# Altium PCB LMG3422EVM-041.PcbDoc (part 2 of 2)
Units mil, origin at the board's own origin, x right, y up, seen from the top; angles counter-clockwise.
Board outline 3001 x 1535.46 mil, 4 copper layers (Top Layer, MidLayer1, MidLayer2, Bottom Layer), stack 46.2 mil thick; 103 components, 73 nets, 350 pads, 858 vias.
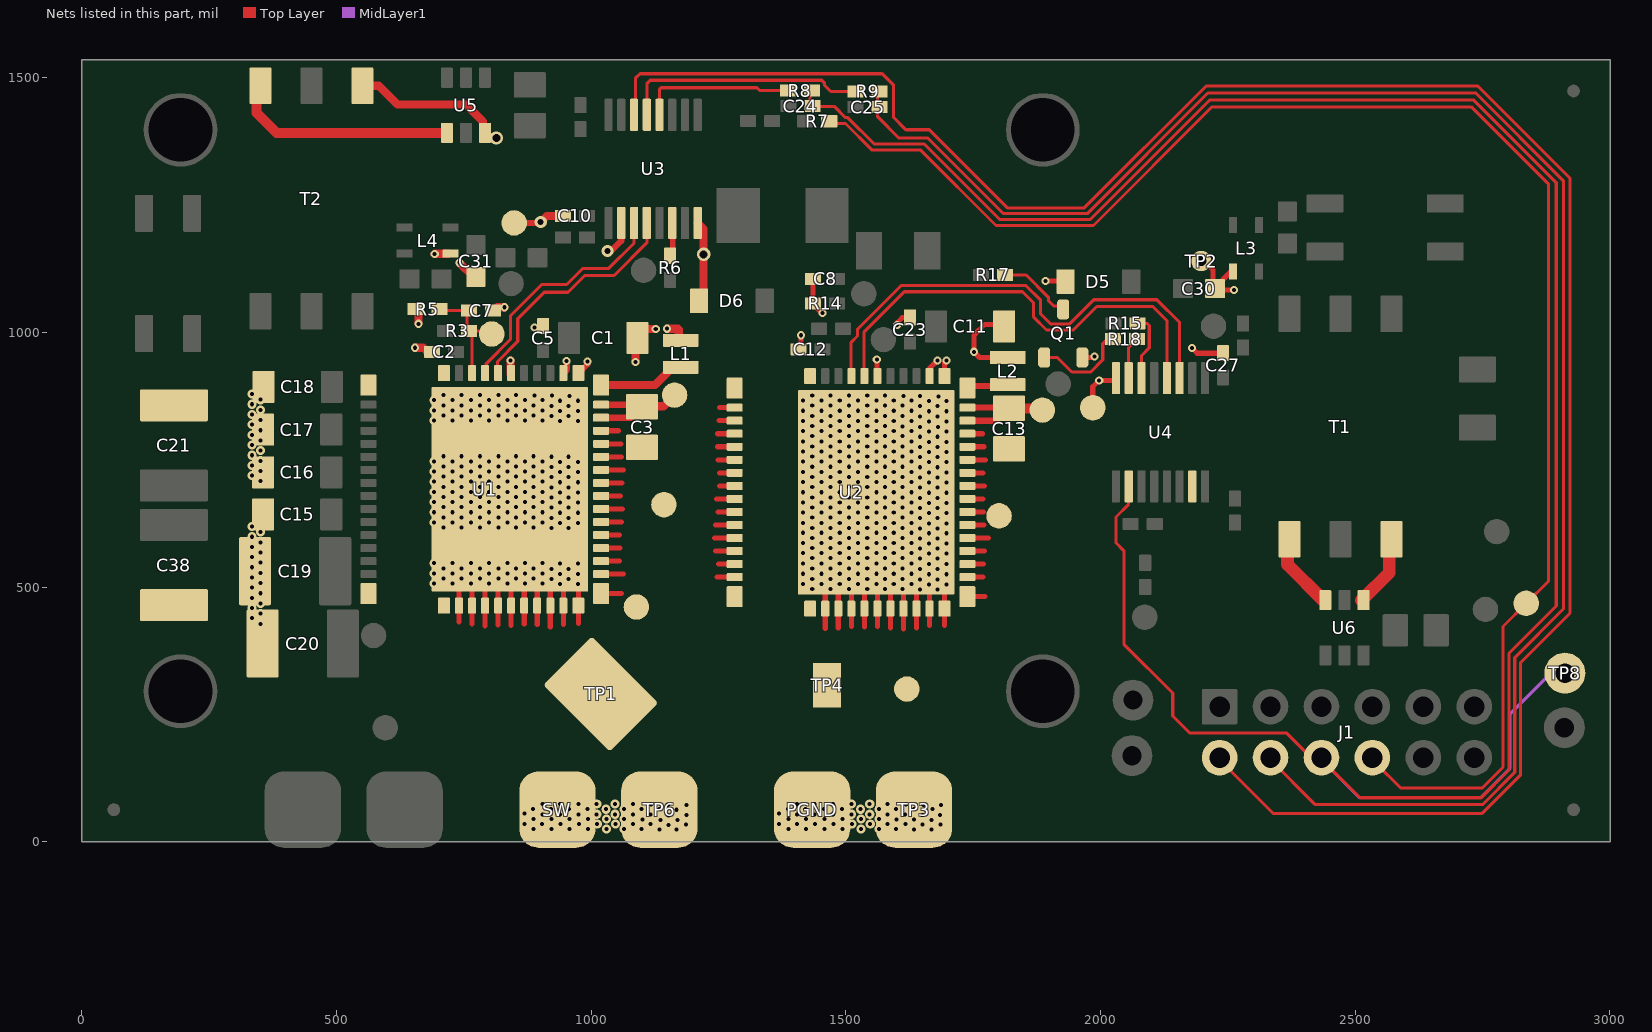
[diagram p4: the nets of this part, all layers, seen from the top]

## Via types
v1: diameter 18, hole 8, Top Layer to Bottom Layer, tented both sides, 781 vias
v2: diameter 16, hole 8, Top Layer to Bottom Layer, tented both sides, 44 vias
v3: diameter 26, hole 16, Top Layer to Bottom Layer, tented both sides, 17 vias
v4: diameter 24, hole 12, Top Layer to Bottom Layer, tented both sides, 6 vias
v5: diameter 20, hole 10, Top Layer to Bottom Layer, tented both sides, 6 vias
v6: diameter 16, hole 8, Top Layer to Bottom Layer, 3 vias
v7: diameter 20, hole 10, Top Layer to Bottom Layer, 1 vias

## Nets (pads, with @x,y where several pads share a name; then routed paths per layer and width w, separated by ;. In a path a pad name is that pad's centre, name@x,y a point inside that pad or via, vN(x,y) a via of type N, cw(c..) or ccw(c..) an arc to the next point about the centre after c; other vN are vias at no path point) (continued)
NetL1_2: L1.2 U1.43 | length 154.6
  Top Layer w16: U1.43@1019.69,896.57 1125.44,896.57 L1.2@1160,931.13
NetL2_2: L2.2 U2.43 | length 76.8
  Top Layer w12: U2.43@1738.35,894.72 1811.3,894.72 L2.2@1814,897.42
NetQ1_1: Q1.1 R18.2 | length 188.5
  Top Layer w6: Q1.1@1890.65,951 1915.53,951 1943.96,922.57 1981.02,922.57 2004.62,946.17 2004.62,959.83 2004.57,959.88 2004.57,978.19 R18.2@2019.38,993
NetQ1_3: Q1.3 R17.1 | length 149.2
  Top Layer w6: R17.1@1812,1116 1815.14,1112.86 1854.14,1112.86 1897.74,1069.26 1897.74,1062.65 1908.74,1051.65 1920.6,1051.65 Q1.3@1927,1045.24 ; Q1.3@1927,1045.49 Q1.3@1928.05,1045.49
NetR6_1: R6.1 U3.6 | length 65.9
  Top Layer w10: R6.1@1160.4,1148.51 U3.6@1160.4,1214.39
NetR8_2: R8.2 U3.12 | length 303.9
  Top Layer w6: U3.12@1130.4,1427.1 1134,1430.7 1134,1477.38 1137.12,1480.5 1325.79,1480.5 1331.65,1474.63 R8.2@1382.38,1474.63
NetR9_2: R9.2 U3.13 | length 483.5
  Top Layer w6: U3.13@1105.4,1427.1 1109.4,1431.1 1109.4,1488.47 1116.15,1495.22 1452.89,1495.22 1457.87,1490.24 1457.87,1485.96 1470.83,1473 R9.2@1515.38,1473
NetR15_1: R15.1 U4.6 | length 141.4
  Top Layer w6: R15.1@2065.92,1023 R15.1@2072.62,1023 ; R15.1@2072.62,1018 2091.47,1018 2095.87,1013.6 2095.87,969.87 2080.5,954.5 U4.6@2080.5,910.3
NetR18_1: R18.1 U4.7 | length 83.4
  Top Layer w6: U4.7@2055.5,910.3 2055.5,970.88 R18.1@2071.62,987
NetT1_1: T1.1 U6.3 | length 148.8
  Top Layer w25: T1.1@2367.24,593.74 2367.24,544.5 U6.3@2437.6,474.13
NetT1_3: T1.3 U6.1 | length 142.3
  Top Layer w25: U6.1@2512.4,474.13 2567.24,528.97 T1.3@2567.24,593.74
NetT2_1: T2.1 U5.3 | length 325.7
  Top Layer w16: T2.1@544,1484.26 583.24,1484.26 620,1447.5 754.7,1447.5 787.77,1414.43 787.77,1391.58 797.35,1382 v3(814,1382)
NetT2_3: T2.3 U5.1 | length 446.4
  Top Layer w20: T2.3@343.28,1491.26 343.28,1430.87 382.57,1391.58 U5.1@712.97,1391.58
OC_H: U1.50 U3.4 | length 484.6
  Top Layer w6: U1.50@816.18,918.35 816.18,942.74 856,982.56 856,1027 908,1079 954.62,1079 987.62,1112 1045.26,1112 1109.4,1176.13 U3.4@1109.4,1210.5 ; U3.4@1105.4,1214.5 U3.4@1109.4,1210.5 ; U3.4@1109.4,1214.78 U3.4@1109.4,1210.5
OC_L: U2.50 U4.4 | length 900.9
  Top Layer w6: U2.50@1536.18,918.35 1536.18,1001.18 1615,1080 1847,1080 1869,1058 1869,1030 1894,1005 1946.94,1005 1992.94,1051 2103,1051 2130.5,1023.5 U4.4@2130.5,910.3
OUTA: U4.15
PGND: C8.2 C11.1 C12.2 C13.2 C15.2 C16.2 C17.2 C18.2 C19.2 C20.2 C21.2 C23.1 C27.2 C30.2 C38.2 D5.2 L2.1 L3.1 pad.1@1620,299.94 pad.1@1801,639.94 pad.1@1985,852.27 PGND.1 Q1.2 R14.1 TP2.1 TP3.1 TP4.1 U2.18 U2.19 U2.20 U2.21 U2.22 U2.23 U2.24 U2.25 U2.26 U2.27 U2.28 U2.29 U2.30 U2.31 U2.32 U2.33 U2.34 U2.35 U2.36 U2.37 U2.38 U2.39 U2.40 U2.44 U2.45 U2.49 U2.55 U4.8 | length 1935
  Top Layer w10: C12.2@1407,967 1412.13,972.13 v2(1412.13,994.52) ; R14.1@1435.76,1057 C8.2@1435.76,1105.27 ; R14.1@1436.38,1054.62 1452.51,1038.49 v2(1454.37,1038.49) ; 1459.76,418.96 U2.18@1459.76,457.68 U2.55@1459.76,490.61 ; 1485.35,419.92 U2.19@1485.35,457.68 U2.55@1485.35,495 ; 1510.94,423.06 U2.20@1510.94,457.68 1510.94,484.94 ; 1536.53,422.28 U2.21@1536.53,457.68 U2.55@1536.53,496 ; v2(1561,947) 1561,919.12 U2.49@1561.77,918.35 ; 1562.12,422.88 U2.22@1562.12,457.68 U2.55@1562.12,495 ; 1587.71,419.56 U2.23@1587.71,457.68 U2.55@1587.71,495 ; v2(1601,1014.58) 1601,1019 1611,1029 C23.1@1622,1029 ; 1613.3,417.7 U2.24@1613.3,457.68 U2.55@1613.3,497 ; 1638.89,420.11 U2.25@1638.89,457.68 U2.55@1638.89,499 ; U2.45@1664.13,918.35 1664.13,929.13 v2(1680,945) ; 1664.48,424.78 U2.26@1664.48,457.68 U2.55@1664.48,498.5 ; U2.44@1693.66,918.35 1693.66,940.61 v2(1698,944.95) ; 1694.01,424.87 U2.27@1694.01,457.68 U2.55@1694.01,495 ; U2.28@1738.69,481.3 1773.3,481.3 ; U2.29@1738.69,519.68 1769.45,519.68 ; U2.30@1738.69,545.28 1770.72,545.28 ; U2.31@1738.69,570.87 1772.13,570.87 ; U2.32@1738.69,596.46 1780,596.46 ; U2.33@1738.69,622.05 1771.05,622.05 ; U2.34@1738.69,647.64 1770.33,647.64 ; U2.35@1738.69,673.23 1769.83,673.23 ; U2.36@1738.69,698.82 1772.04,698.82 ; U2.37@1738.69,724.41 1769.59,724.41 ; U2.38@1738.69,750 1773.88,750 ; U2.39@1738.69,775.59 1771,775.59 ; U2.40@1738.69,801.18 1767.95,801.18 ; C11.1@1806.93,1016 1773,1016 1751.8,994.8 v2(1751.8,962) 1762.8,951 1813.57,951 L2.1@1814,950.57 ; v2(1892,1101) D5.2@1926,1101 ; Q1.2@1965.45,951 v2@1983,951 ; v2(1997.62,906) 1985,893.38 pad.1@1985,852.27 pad.1@1998,842.75 ; v2@1998,906 2026.2,906 U4.8@2030.5,910.3 ; v6(2179.87,969.38) 2190.01,959.24 C27.2@2240.5,959.24 ; TP2.1@2194,1140 2204.46,1140 2221,1123.46 C30.2@2221,1086 ; L3.1@2256.41,1119.72 2222.69,1086 C30.2@2221,1086 ; v2(2262,1083.65) 2223.35,1083.65 C30.2@2221,1086
  other v1: 1634,24 1668,24 1387.23,25 1422,25 1458,25 1494,25 1530,25 1565,25 1599,25 1651,34 1686,34 1369.23,35 1404,35 1440,35 1476,35 1512,35 1548,35 1582,35 1617,35 1668,43 1600,44 1634,44 1387.23,45 1422,45 1458,45 1494,45 1530,45 1565,45 1651,53 1685,53 1404.23,54 1439,54 1475,54 1511,54 1547,54 1582,54 1616,54 1369,55.94 1386.23,64 1421,64 1457,64 1493,64 1529,64 1565,64 1599,64 1634,64 1670,64 1653,72 1687,72 1618,73 1404.23,74 1439,74 1475,74 1511,74 1547,74 1582,74 351,428 334,439 351,448 334,459 351,468 334,479 351,488 1646.18,495.33 1680.18,495.33 1434.18,496.33 1470.18,496.33 1506.18,496.33 1542.18,496.33 1577.18,496.33 1611.18,496.33 334,499 1663.18,505.33 1698.18,505.33 1416.18,506.33 1452.18,506.33 1488.18,506.33 1524.18,506.33 1560.18,506.33 1594.18,506.33 1629.18,506.33 351,508 1646.18,515.33 1680.18,515.33 1434.18,516.33 1470.18,516.33 1506.18,516.33 1542.18,516.33 1577.18,516.33 1611.18,516.33 334,519 1663.18,525.33 1698.18,525.33 1416.18,526.33 1452.18,526.33 1488.18,526.33 1524.18,526.33 1560.18,526.33 1594.18,526.33 1629.18,526.33 351,528 1646.18,535.33 1680.18,535.33 1434.18,536.33 1470.18,536.33 1506.18,536.33 1542.18,536.33 1577.18,536.33 1611.18,536.33 334,539 1663.18,545.33 1698.18,545.33 1416.18,546.33 1452.18,546.33 1488.18,546.33 1524.18,546.33 1560.18,546.33 1594.18,546.33 1629.18,546.33 351,548 1646.18,555.83 1680.18,555.83 1434.18,556.83 1470.18,556.83 1506.18,556.83 1542.18,556.83 1577.18,556.83 1611.18,556.83 334,559 1663.18,565.83 1698.18,565.83 1416.18,566.83 1452.18,566.83 1488.18,566.83 1524.18,566.83 1560.18,566.83 1594.18,566.83 1629.18,566.83 351,568 1646.18,575.83 1680.18,575.83 1434.18,576.83 1470.18,576.83 1506.18,576.83 1542.18,576.83 1577.18,576.83 1611.18,576.83 334,579 1663.18,585.83 1698.18,585.83 1416.18,586.83 1452.18,586.83 1488.18,586.83 1524.18,586.83 1560.18,586.83 1594.18,586.83 1629.18,586.83 351,588 1646.18,595.83 1680.18,595.83 1434.18,596.83 1470.18,596.83 1506.18,596.83 1542.18,596.83 1577.18,596.83 1611.18,596.83 334,599 1663.18,605.83 1698.18,605.83 1416.18,606.83 1452.18,606.83 1488.18,606.83 1524.18,606.83 1560.18,606.83 1594.18,606.83 1629.18,606.83 351,608 1646.18,615.33 1680.18,615.33 1434.18,616.33 1470.18,616.33 1506.18,616.33 1542.18,616.33 1577.18,616.33 1611.18,616.33 334,619 1663.18,625.33 1698.18,625.33 1416.18,626.33 1452.18,626.33 1488.18,626.33 1524.18,626.33 1560.18,626.33 1594.18,626.33 1629.18,626.33 1646.18,635.33 1680.18,635.33 1434.18,636.33 1470.18,636.33 1506.18,636.33 1542.18,636.33 1577.18,636.33 1611.18,636.33 1663.18,645.33 1698.18,645.33 1416.18,646.33 1452.18,646.33 1488.18,646.33 1524.18,646.33 1560.18,646.33 1594.18,646.33 1629.18,646.33 1646.18,655.33 1680.18,655.33 1434.18,656.33 1470.18,656.33 1506.18,656.33 1542.18,656.33 1577.18,656.33 1611.18,656.33 1663.18,665.33 1698.18,665.33 1416.18,666.33 1452.18,666.33 1488.18,666.33 1524.18,666.33 1560.18,666.33 1594.18,666.33 1629.18,666.33 1646.18,675.33 1680.18,675.33 1434.18,676.33 1470.18,676.33 1506.18,676.33 1542.18,676.33 1577.18,676.33 1611.18,676.33 1663.18,685.33 1698.18,685.33 1416.18,686.33 1452.18,686.33 1488.18,686.33 1524.18,686.33 1560.18,686.33 1594.18,686.33 1629.18,686.33 1646.18,695.33 1680.18,695.33 1434.18,696.33 1470.18,696.33 1506.18,696.33 1542.18,696.33 1577.18,696.33 1611.18,696.33 1663.18,705.33 1698.18,705.33 1416.18,706.33 1452.18,706.33 1488.18,706.33 1524.18,706.33 1560.18,706.33 1594.18,706.33 1629.18,706.33 351,708 1646.18,715.33 1680.18,715.33 1434.18,716.33 1470.18,716.33 1506.18,716.33 1542.18,716.33 1577.18,716.33 1611.18,716.33 334,719 1663.18,725.33 1698.18,725.33 1416.18,726.33 1452.18,726.33 1488.18,726.33 1524.18,726.33 1560.18,726.33 1594.18,726.33 1629.18,726.33 351,728 1646.18,735.33 1680.18,735.33 1434.18,736.33 1470.18,736.33 1506.18,736.33 1542.18,736.33 1577.18,736.33 1611.18,736.33 334,739 1663.18,745.33 1698.18,745.33 1416.18,746.33 1452.18,746.33 1488.18,746.33 1524.18,746.33 1560.18,746.33 1594.18,746.33 1629.18,746.33 351,748 1646.18,755.33 1680.18,755.33 1434.18,756.33 1470.18,756.33 1506.18,756.33 1542.18,756.33 1577.18,756.33 1611.18,756.33 334,759 1663.18,765.33 1698.18,765.33 1416.18,766.33 1452.18,766.33 1488.18,766.33 1524.18,766.33 1560.18,766.33 1594.18,766.33 1629.18,766.33 351,768 1646.18,775.33 1680.18,775.33 1434.18,776.33 1470.18,776.33 1506.18,776.33 1542.18,776.33 1577.18,776.33 1611.18,776.33 334,779 1663.18,785.33 1698.18,785.33 1416.18,786.33 1452.18,786.33 1488.18,786.33 1524.18,786.33 1560.18,786.33 1594.18,786.33 1629.18,786.33 351,788 1646.18,795.33 1680.18,795.33 1434.18,796.33 1470.18,796.33 1506.18,796.33 1542.18,796.33 1577.18,796.33 1611.18,796.33 334,799 1663.18,805.33 1698.18,805.33 1416.18,806.33 1452.18,806.33 1488.18,806.33 1524.18,806.33 1560.18,806.33 1594.18,806.33 1629.18,806.33 351,808 1646.18,814.33 1681.18,814.33 1611.18,815.33 1434.18,816.33 1470.18,816.33 1506.18,816.33 1542.18,816.33 1577.18,816.33 334,819 1663.18,825.33 1698.18,825.33 1416.18,826.33 1452.18,826.33 1488.18,826.33 1524.18,826.33 1560.18,826.33 1594.18,826.33 1629.18,826.33 351,828 1646.18,835.33 1680.18,835.33 1434.18,836.33 1470.18,836.33 1506.18,836.33 1542.18,836.33 1577.18,836.33 1611.18,836.33 334,839 1663.18,845.33 1698.18,845.33 1416.18,846.33 1452.18,846.33 1488.18,846.33 1524.18,846.33 1560.18,846.33 1594.18,846.33 1629.18,846.33 351,848 1646.18,855.33 1680.18,855.33 1434.18,856.33 1470.18,856.33 1506.18,856.33 1542.18,856.33 1577.18,856.33 1611.18,856.33 334,859 1663.18,865.33 1698.18,865.33 1416.18,866.33 1452.18,866.33 1488.18,866.33 1524.18,866.33 1560.18,866.33 1594.18,866.33 1629.18,866.33 351,868 1682.18,874.33 1613.18,875.33 1646.18,875.33 1434.18,876.33 1470.18,876.33 1506.18,876.33 1542.18,876.33 1577.18,876.33 334,879
  other v2: 1988.12,953
RDRV_H: C7.1 pad.1@805,997 R3.1 R5.2 U1.52 | length 222.4
  Top Layer w6: R5.2@713.9,1043.28 755.83,1043.28 756.38,1042.72 756.38,1005.62 R3.1@759,1003 ; U1.52@765,918.35 766.35,919.69 U1.52@766.35,920.2 766.35,995.65 R3.1@759,1003 ; pad.1@803,1019 787,1003 R3.1@759,1003
SW: C1.2 C2.2 C3.2 C5.1 C7.2 C10.2 C31.2 D6.2 L1.1 L4.1 pad.1@849,1215 pad.1@1089,461 pad.1@1143,662 R5.1 SW.1 TP1.1 TP6.1 U1.18 U1.19 U1.20 U1.21 U1.22 U1.23 U1.24 U1.25 U1.26 U1.27 U1.28 U1.29 U1.30 U1.31 U1.32 U1.33 U1.34 U1.35 U1.36 U1.37 U1.38 U1.39 U1.40 U1.44 U1.45 U1.49 U1.55 U2.2 U2.3 U2.4 U2.5 U2.6 U2.7 U2.8 U2.9 U2.10 U2.11 U2.12 U2.13 U2.14 U2.15 U3.2 U3.8 | length 2367.2
  Top Layer w10: 740.76,431.76 U1.18@740.76,463.5 740.76,490.81 ; 766.35,427.35 U1.19@766.35,463.5 U1.55@766.35,497 ; 791.94,423.38 U1.20@791.94,463.5 791.94,490.99 ; 817.53,426.06 U1.21@817.53,463.5 817.53,491.06 ; 843.12,424.38 U1.22@843.12,463.5 U1.55@843.12,500.06 ; 868.71,427.35 U1.23@868.71,463.5 U1.55@868.71,497 ; 894.3,426.3 U1.24@894.3,463.5 894.3,491.06 ; 919.89,421.81 U1.25@919.89,463.5 919.89,491 ; 945.48,426.56 U1.26@945.48,463.5 U1.55@945.48,493 ; 975.01,428.35 U1.27@975.01,463.5 975.01,491.06 ; U1.28@1019.69,487.13 1060.06,487.13 ; U1.29@1019.69,525.51 1063.25,525.51 ; U1.30@1019.69,551.1 1055.68,551.1 ; U1.31@1019.69,576.69 1057.08,576.69 ; U1.32@1019.69,602.28 1056.05,602.28 ; U1.33@1019.69,627.87 1060.13,627.87 ; U1.34@1019.69,653.46 1061.46,653.46 ; U1.35@1019.69,679.06 1057.83,679.06 ; U1.36@1019.69,704.65 1060.35,704.65 ; U1.37@1019.69,730.24 1063.76,730.24 ; U1.38@1019.69,755.83 1059.24,755.83 ; U1.39@1019.69,781.42 1058.56,781.42 ; U1.40@1019.69,807.01 1053.99,807.01 ; 1242.24,596.46 U2.12@1282,596.46 ; 1244,622.05 U2.11@1282,622.05 ; 1244.62,570.87 U2.13@1282,570.87 ; 1246.05,673.23 U2.9@1282,673.23 ; 1246.88,519.68 U2.15@1282,519.68 ; 1248.22,775.59 U2.5@1282,775.59 ; 1248.33,801.18 U2.4@1282,801.18 ; 1248.97,647.64 U2.10@1282,647.64 ; 1249.69,750 U2.6@1282,750 ; 1250.49,545.28 U2.14@1282,545.28 ; 1251.64,826.77 U2.3@1282,826.77 ; 1252.02,724.41 U2.7@1282,724.41 ; 1252,852.36 U2.2@1282,852.36 ; 1252.21,698.82 U2.8@1282,698.82
  Top Layer w12: pad.1@849,1215 899,1215 v4(901,1217) ; U1.45@948.13,922.35 952.96,927.17 952.96,943.04 v2(952,944) ; U1.44@973.66,918.35 993,937.69 v2(993,943) ; v4(1032,1160) 1039.5,1160 1059.4,1179.89 U3.2@1059.4,1210.5
  Top Layer w16: v2(654,970) 670.5,970 C2.2@679.5,961 ; R5.1@655,1046 661,1040 v2(661,1017) ; v2(693,1154) 693.41,1154.41 L4.1@720.28,1154.41 ; v2(742,1137) 742,1136.5 C31.2@770,1108.5 ; C7.2@803.62,1042.72 806.35,1040 815.85,1049.5 v2(829.76,1049.5) ; U1.49@841.77,918.35 v2(841.77,945) ; v4(901,1217) 913,1229 C10.2@944.76,1229 ; v2(1086.93,942) 1086.93,989 1104.93,1007 v2(1127,1007) ; v2(1149,1007.38) 1170.62,1007.38 1172,1006 L1.1@1172,984.28 ; U3.8@1209.4,1214.78 1221,1203.17 v3(1221,1153.4) 1221,1069.47 D6.2@1210.53,1059
  other v1: 1134,24 1168,24 887.23,25 922,25 958,25 994,25 1030,25 1065,25 1099,25 1152,33 1186,34 869.23,35 904,35 940,35 976,35 1012,35 1048,35 1082,35 1117,35 1136,43 1170,43 1101,44 887.23,45 922,45 958,45 994,45 1030,45 1065,45 1152,52 1187,53 904.23,54 939,54 975,54 1011,54 1047,54 1082,54 1117,54 869,55.94 1168,63 886.23,64 921,64 957,64 993,64 1029,64 1065,64 1099,64 1134,64 1151,72 1187,72 1118,73 904.23,74 939,74 975,74 1011,74 1047,74 1082,74 939,506 974,506 692,507 728,507 764,507 800,507 836,507 870,507 905,507 922,516 956,516 710,517 746,517 782,517 818,517 853,517 887,517 939,526 974,526 692,527 728,527 764,527 800,527 836,527 870,527 905,527 922,536 956,536 710,537 746,537 782,537 818,537 853,537 887,537 939,546 974,546 692,547 728,547 764,547 800,547 836,547 870,547 905,547 922,616 956,616 710,617 746,617 782,617 818,617 853,617 887,617 939,626 974,626 692,627 728,627 764,627 800,627 836,627 870,627 905,627 922,636 956,636 710,637 746,637 782,637 818,637 853,637 887,637 939,646 974,646 692,647 728,647 764,647 800,647 836,647 870,647 905,647 922,656 956,656 710,657 746,657 782,657 818,657 853,657 887,657 939,666 974,666 692,667 728,667 764,667 800,667 836,667 870,667 905,667 922,676 956,676 710,677 746,677 782,677 818,677 853,677 887,677 939,686 974,686 692,687 728,687 764,687 800,687 836,687 870,687 905,687 922,696 956,696 710,697 746,697 782,697 818,697 853,697 887,697 939,706 974,706 692,707 728,707 764,707 800,707 836,707 870,707 905,707 922,716 956,716 710,717 746,717 782,717 818,717 853,717 887,717 939,726 974,726 692,727 728,727 764,727 800,727 836,727 870,727 905,727 922,736 956,736 710,737 746,737 782,737 818,737 853,737 887,737 939,746 974,746 692,747 728,747 764,747 800,747 836,747 870,747 905,747 922,756 956,756 710,757 746,757 782,757 818,757 853,757 887,757 939,826 974,826 692,827 728,827 764,827 800,827 836,827 870,827 905,827 922,836 956,836 710,837 746,837 782,837 818,837 853,837 887,837 939,846 974,846 692,847 728,847 764,847 800,847 836,847 870,847 905,847 922,856 956,856 710,857 746,857 782,857 818,857 853,857 887,857 939,866 974,866 692,867 728,867 764,867 800,867 836,867 870,867 905,867 958,875 889,876 923,876 710,877 746,877 782,877 818,877 853,877
  other v2: 889,1010
TEMP_H: U1.51 U3.3 | length 482.4
  Top Layer w6: U1.51@790.59,918.35 794.2,921.95 794.2,938.82 841.77,986.4 841.77,1032.77 903,1094 952,1094 984,1126 1035,1126 1084.4,1175.4 U3.3@1084.4,1210.5 ; U3.3@1080.4,1214.5 U3.3@1084.4,1210.5 ; U3.3@1084.4,1214.78 U3.3@1084.4,1210.5
TEMP_L: U2.51 U4.3 | length 955.3
  Top Layer w6: U2.51@1510.59,918.35 1510.59,980.59 1523,993 1523,1006.49 1608.51,1092 1854,1092 1882.62,1063.38 1882.62,1036.41 1901.96,1017.06 1939.68,1017.06 1986.88,1064.26 2110.74,1064.26 2155.5,1019.5 U4.3@2155.5,910.3
Top_FET_FAULT: C24.1 J1.6 R8.1 TP8.1 U4.10 | length 4868.5
  Top Layer w6: R8.1@1429.62,1474.63 1429.62,1445.07 1430.62,1444.07 1477.14,1444.07 1499.52,1421.69 1504.15,1421.69 1555.84,1370 1654,1370 1802.2,1221.8 1979.8,1221.8 2214,1456 2733,1456 2895,1294 2895,463 2802,370 2802,141.03 2747.47,86.5 2509.5,86.5 2442.5,153.5 J1.6@2430,153.5 ; U4.10@2055.5,697.7 2055.5,662.83 2030.5,637.83 2030.5,587.09 2046,571.59 2046,388 2142,292 2142,247 2175,214 2365,214 2414,165 J1.6@2430,165
  MidLayer1 w6: J1.6@2430,165 2508,87 2747,87 2804.57,144.58 2804.57,251.43 2884.15,331 TP8.1@2908,331
Top_FET_OC: C25.1 J1.4 R9.1 | length 3393.1
  Top Layer w6: C25.1@1562.62,1442 1562.62,1423.38 1604.5,1381.5 1661.5,1381.5 1809.7,1233.3 1974.22,1233.3 2210.93,1470 2737,1470 2909,1298 2909,457 2813.5,361.5 2813.5,136.26 2750.24,73 2422,73 J1.4@2330,165 ; C25.1@1562.62,1442 R9.1@1562.62,1473
Top_FET_PWM: J1.8 pad.1@2836,468.19 R7.1 | length 3136
  Top Layer w6: R7.1@1466.62,1414.43 1470.86,1410.19 1499.38,1410.19 1551.07,1358.5 1646.5,1358.5 1795,1210 1986.26,1210 2219.26,1443 2728,1443 2880,1291 2880,512.19 pad.1@2836,468.19 2790.5,422.69 2790.5,146.5 2750,106 2589,106 2541.5,153.5 J1.8@2541.5,165
Top_FET_TEMP: J1.2 U3.14 | length 4116.7
  Top Layer w6: U3.14@1080.4,1427.1 1087,1433.7 1087,1499 1096,1508 1571.47,1508 1594,1485.47 1594,1422 1618,1398 1664,1398 1817.2,1244.8 1968.43,1244.8 2207.64,1484 2741,1484 2922,1303 2922,449 2825,352 2825,131.5 2749.5,56 2339,56 J1.2@2230,165
U1NC1: U1.1
U1NC16: U1.16
U1NC17: U1.17
U1NC54: U1.54
U2NC1: U2.1
U2NC16: U2.16 | length 4
  Top Layer w6: U2.16@1279.2,478.5 U2.16@1282,481.3
U2NC17: U2.17
U2NC54: U2.54 | length 1.4
  Top Layer w10: U2.54@1429.88,918.35 U2.54@1430.88,919.35
VNEG_H: C3.1 pad.1@1164,877 U1.41 U1.42 | length 245.1
  Top Layer w12: U1.41@1019.69,832.6 1078.32,832.6 C3.1@1100,854.27 ; U1.42@1019.69,858.19 C3.1@1096.09,858.19
  Top Layer w16: C3.1@1096.09,858.19 C3.1@1099.27,855 ; C3.1@1100,854.27 C3.1@1099.27,855 ; pad.1@1164,877 1142,855 C3.1@1099.27,855
VNEG_L: C13.1 pad.1@1886,847.62 U2.41 U2.42 | length 241.4
  Top Layer w12: U2.41@1738.69,826.77 1796.04,826.77 C13.1@1820.27,851 ; U2.42@1738.69,852.36 C13.1@1819.45,852.36
  Top Layer w20: C13.1@1819.45,852.36 C13.1@1820.54,851.27 1820.27,851 1882.62,851 pad.1@1886,847.62
pads on no net: FID1.1 FID2.1 FID3.1 FID4.1 FID5.1 FID6.1 LBL.0
copper on no net: | length 947.7
  Top Layer w10: v2(2101,1152) 2106,1152 2288,1334 2709.13,1334 2787,1256.13 2787,1136 v2(2763,1112)

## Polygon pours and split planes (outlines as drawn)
PGND on MidLayer2 "PGND_L03_P054" (solid, pour order 54): 1391.07,880.61 1389.67,1128.37 2223.42,1128.37 2260.67,1091.12 2260.67,917.74 2223.54,880.61 1980.67,880.61 1912.73,880.61
SW on MidLayer2 "SW_L03_P042" (solid, remove dead copper, pour order 42): 623.69,902 1236.03,902 1236.03,1229.15 1216.34,1248.84 623.69,1248.84
5V on MidLayer2 "5V_L03_P014" (solid, remove dead copper, pour order 14): 2850,789.84 2788.55,728.39 2761.45,728.39 2021.81,728.39 2021.81,-3.44 2026.25,1 2979,1 2979,789.74
HVBUS on MidLayer2 "HVBUS_L03_P064" (solid, remove dead copper, pour order 64): 666,942.67 666,413.58 712.86,366.72 712,20 382,20 110,292 110,942.67
PGND on MidLayer2 "PGND_L03_P074" (solid, remove dead copper, pour order 74): 1355,845 1396.35,886.35 1928.05,886.35 1928.05,6.14 1918.47,-3.44 1355,-3.44
SW on MidLayer2 "SW_L03_P078" (solid, pour order 78): 655.59,903 1236.18,903 1298,841.72 1298,106.51 1191.49,0 848,0 848,266.44 637.42,477.01 637.42,878.74
no net on MidLayer2 "NONET_L03_P062" (solid, remove dead copper, pour order 62): 108.07,740
no net on MidLayer2 "NONET_L03_P000" (solid, remove dead copper, pour order 0): 837,3
AGND on MidLayer1 "AGND_L02_P016" (solid, remove dead copper, pour order 16): 75,1525 75,1375 1227,1375 1257,1345 1621.27,1345 1770.27,1196 2036,1196 2245,1405 2724,1405 2847,1282 2847,789.69 2788.55,731.24 2788.55,725 1988,723.1 1988,645 2023.78,609.22 2023.78,2.84 2980,2.84 2980,1525
PGND on MidLayer1 "PGND_L02_P052" (solid, pour order 52): 1384.37,880.79 1384.37,1211 1667,1211 1749.46,1128.54 2073.88,1128.54 2300.34,1355 2703,1355 2792,1267.98 2792,1001 2260,1001 2260,917.92 2222.87,880.79 1940,880.79
PGND on MidLayer1 "PGND_L02_P072" (solid, remove dead copper, pour order 72): 318,894.49 535.51,894.49 546.42,883.58 1397,883.58 1399.76,886.35 1928.05,886.35 1928.05,6.14 1918.47,-3.44 1350,-3.44 1350,259 1294,315 318,315
SW on MidLayer1 "SW_L02_P038" (solid, remove dead copper, pour order 38): 623.68,894.49 1200.49,894.49 1236.01,930.01 1236.01,1230.31 1216.32,1250 623.68,1250
SW on MidLayer1 "SW_L02_P076" (solid, remove dead copper, pour order 76): 649.22,894.49 1278.4,894.49 1300,873.08 1300,505.93 1248.07,445 669.44,445 637.42,477.01 637.42,878.74
AGND on MidLayer1 "AGND_L02_P006" (solid, remove dead copper, pour order 6): 685,1532
SW on Top Layer "SW_L01_P084" (solid, remove dead copper, pour order 84): 850,0 850,300 712,438 1052,434.62 1052,810 1170,810 1170,839.03 1200.21,869.25 1219.25,869.25 1255,869.25 1255,412.17 1210,367.17 1210,0
PGND on Top Layer "PGND_L01_P070" (solid, remove dead copper, pour order 70): 1348.97,-0.35 1348.97,345.05 1403.57,399.65 1403.57,431 1764.76,431 1763.72,808.91 1894.97,808.27 1912.44,784.38 1912.44,2.49
PGND on Top Layer "PGND_L01_P068" (solid, pour order 68): 108.07,826.46 108.07,886.77 116.02,894.72 380,894.72 380,330 143.94,330 108.07,365.87 108.07,480 263.46,480 297,513.54 297,807.54 279.89,824.65
HVBUS on Top Layer "HVBUS_L01_P066" (solid, remove dead copper, pour order 66): 108.07,721.02 241.91,721.02 241.91,604.65 237.74,600.47 108.07,600.47
HVBUS on Top Layer "HVBUS_L01_P060" (solid, remove dead copper, pour order 60): 349.31,1.87 349.31,265.87 429.31,345.87 429.31,871.87 475.06,917.62 534.31,917.62 537.16,468.98 710.76,345.87 710.76,1.87
no net on Top Layer "NONET_L01_P024" (solid, remove dead copper, pour order 24): 610,1300
PGND on Bottom Layer "PGND_L04_P088" (solid, pour order 88): 1724,361 1459,361 1326,494 1326,845 1425,944 1770,944 1895,819 1895,532
SW on Bottom Layer "SW_L04_P086" (solid, pour order 86): 1096,370 709,370 595,484 595,863 675,943 1112,943 1159,896 1159,433

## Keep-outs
Top Layer:
  region: 1267,911 1298,911 1298,870 1267,870
  region: 1266,502 1298,502 1298,461 1266,461
  region: 1723,502 1754,502 1754,460 1724,460 1723,461
  region: 1418,473
  region: 1004,508 1036,508 1036,466 1004,466
  region: 547,917 579,917 579,876 547,876
  region: 547,508 579,508 579,466 547,466
Keep-Out Layer:
  lines w10: -5,1 -5,1540.46 3006,1540.46 ; 3006,0 3006,1540
  text ".Layer_Name" at 502,-1396.77 h60

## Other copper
Top Layer:
  rectangle net 5V: 2435,520 2500,630
  rectangle net AGND: 1207,1420 1319,1451
  rectangle net 5V: 415,1420.12 475,1520
  region net NetD1_2: 1505,1283 1505,1271.15 1506.07,1270.07 1582,1270.07 1582,1244 1582,1123.74 1503,1123.74 1503,1175.81 1421,1175.81 1417.81,1179 1417.81,1281 1421,1285 1503,1285
  region net NetC1_1: 1245,1158 1243,1160 1245,1162 1245,1286 1344,1286 1357,1273 1357,1041.74 1245,1041.74
MidLayer1:
  pour cut-out: 1712.47,880 1926.47,880 1926.47,828 1926.24,827.77 1712.47,827.77
  pour cut-out: 1035.99,533.99 1035.99,445.98 1330,445.98 1330,530.08
  pour cut-out: 983.01,901.5 983.01,822.79 1325,822.79 1325,896.95
  pour cut-out: 1045,746.54 1045,618.79 1327,618.79 1327,742.79
MidLayer2:
  pour cut-out: 1714,879 1928,879 1928,827 1927.77,826.77 1714,826.77
  pour cut-out: 983.01,901.5 983.01,822.79 1325,822.79 1325,896.95

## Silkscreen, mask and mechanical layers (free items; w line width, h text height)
Top Overlay:
  lines w5: 2029,806.28 2029,860
  lines w10: 0,566 0,570 ; 3000,554 3000,560
  text "Danger / High Voltage" at 1728,1177 h35
  text "Max DC input:  / 480V or 25A" at 99,121 h23
  text "LMG3422R050 / HVP041-002 A1" at 1568,11 h72.83
Bottom Overlay:
  lines w10: 68.08,577.94 483.01,162.01 ; 71,1134 471,1534 ; 1596.52,1530.53 2034.99,1091 ; 1601,163 2035.53,596.48 ; 2033.5,160 66.98,159 68.13,1535 2034.68,1535 ; 2037,161 2037,1536
Top Paste:
  text ".Layer_Name" at 5093,2938.51 h60
Bottom Paste:
  text ".Layer_Name" at 5093,2938.51 h60
Top Solder:
  text ".Layer_Name" at 5093,2938.51 h60
Bottom Solder:
  rectangle: 61,154 2043,1541
  text ".Layer_Name" at 5093,2938.51 h60
M1 Board Outline:
  the board outline again, w10
  text ".Layer_Name" at 502,-1396.77 h60
M2 Board Dimensions:
  rectangle: -70,-823.28 55,-698.28
  rectangle: 50,-948.78 425,-823.78
  lines w7: -75,-698.78 -75,-948.78 925,-948.78 925,-698.78 ; -70,-823.28 930,-823.28 ; -70,-698.28 930,-698.28 ; 50,-948.78 50,-698.78 ; 175,-948.78 175,-698.78 ; 425,-948.78 425,-698.78 ; 675,-948.78 675,-698.78
  text ".Layer_Name" at 502,-1396.77 h60
M3 3D STEP Top:
  text ".Layer_Name" at 502,-1396.77 h60
M5 Assembly Top:
  lines w10: -367,-1468.44 6233,-1468.44 ; -367,-1265.11 6235,-1265.11 ; -367,-1061.78 -367,-1671.78 3638,-1671.78 6235,-1671.78 6235,-1061.78 -366.5,-1061.78 -366.5,-1671.78 ; 2098,-1671.78 2098,-1061.78 ; 3365,-1265.11 3365,-1061.78 ; 4205,-1265.11 4205,-1061.78 ; 4224.5,2663.5 5800,2663.5 ; 4827,-1678.28 4827,-1475.44
  text "PCB VIEWED FROM TOP SIDE" at 4287.5,3141.33 h60
  text "IGNORE ->" at 4287.5,2938.51 h60
  text "PLOT NAME =" at 4287.5,2732.66 h60
  text "COMPONENTS MARKED 'DNP' SHOULD NOT BE POPULATED." at 1078.5,-856.78 h60
  text "ASSEMBLY VARIANT:" at 1078,-972.28 h60
  text ".VariantName" at 2114,-972.28 h60
  text "BOARD #:" at 2173,-1193.94 h60
  text ".PRJ_Number" at 2718.5,-1193.94 h60
  text "REV:" at 3563,-1193.94 h60
  text ".PCB_Rev" at 3854.5,-1193.94 h60
  text "SVN REV:" at 4401,-1193.94 h60
  text ".VersionControl_RevNumber" at 4907,-1193.94 h60
  text ".plot_File_Name" at 502,-1602.61 h60
  text "GENERATED    :" at 2175,-1602.61 h60
  text ".Print_Date" at 3044.5,-1602.61 h60
  text ".Print_Time" at 3773.5,-1602.61 h60
  text "TEXAS INSTRUMENTS" at 5038,-1602.61 h60
M6 Assembly Bottom:
  lines w10: -367.5,-1265.61 6234.5,-1265.61 ; -365.5,-1468.94 6234.5,-1468.94 ; 1662.5,-1265.61 1662.5,-1062.28 ; 2502.5,-1265.61 2502.5,-1062.28 ; 3769.5,-1672.28 3769.5,-1062.28 ; 4658.5,-1672.28 6234,-1672.28 6234,-1062.28 -367.5,-1062.28 -367.5,-1672.28 2229.5,-1672.28 6234.5,-1672.28 6234.5,-1062.28 ; 5631.5,2656.5 5631.5,2859.33
  text ".VersionControl_RevNumber" at 5551.5,3140.83 h60
  text "TEXAS INSTRUMENTS" at 5420.5,2732.16 h60
  text "COMPONENTS MARKED 'DNP' SHOULD NOT BE POPULATED." at 6724,-860.28 h60
  text ".VariantName" at 5680,-976.28 h60
  text "ASSEMBLY VARIANT:" at 6719,-976.28 h60
  text "SVN REV:" at 1466.5,-1194.44 h60
  text ".PCB_Rev" at 2013,-1194.44 h60
  text "REV:" at 2304.5,-1194.44 h60
  text ".PRJ_Number" at 3149,-1194.44 h60
  text "BOARD #:" at 3694.5,-1194.44 h60
  text "PCB VIEWED FROM BOTTOM SIDE" at 6171,-1194.44 h60
  text "IGNORE ->" at 2472.85,-1396.77 h60
  text ".Print_Time" at 2094,-1603.11 h60
  text ".Print_Date" at 2823,-1603.11 h60
  text "GENERATED    :" at 3692.5,-1603.11 h60
  text ".plot_File_Name" at 5365.5,-1603.11 h60
  text "PLOT NAME =" at 6171,-1603.11 h60
M9 Title Sheet:
  drawing of 57 lines, arcs and shapes, not listed
  text "1" at 664.84,7498.22 h70
  text "2" at 3160.5,7498.22 h70
  text "3" at 5649.84,7498.22 h70
  text "4" at 8156.51,7498.22 h70
  text "5" at 10655.5,7498.22 h70
  text "6" at 13160.5,7498.22 h70
  text "A" at -491.5,6355.22 h70
  text "A" at 14308.5,6355.22 h70
  text "B" at -491.5,3975.22 h70
  text "B" at 14308.5,3975.22 h70
  text "1" at 5255.84,2533.5 h70
  text "C" at 14308.5,1600.22 h70
  text "PROJECT TITLE:" at 11268.5,-260.78 h45
  text "LMG342xRx0" at 11318.5,-394.1 h70
  text "DESIGNED FOR:" at 11268.5,-561.78 h45
  text ".PRJ_Customer" at 11318.5,-701.78 h70
  text "D" at -491.5,-769.78 h70
  text "D" at 14308.5,-769.78 h70
  text "FILE NAME:" at 11268.5,-861.78 h45
  text ".PCB_File_Name_No_Path" at 11318.5,-981.78 h70
  text "Texas Instruments (TI) and/or its licensors do not warrant the accuracy or completeness of this specification" at 6299,-1143.61 h45
  text "ENGINEER:" at 11268.5,-1151.78 h45
  text "LAYOUT BY:" at 12773.5,-1151.78 h45
  text "or any information contained therein. TI and/or its licensors do not warrant that this design will meet" at 6254.01,-1256.28 h45
  text "Rui Gao" at 11318.5,-1306.77 h70
  text "Rui Gao" at 12824,-1306.77 h70
  text "the specifications, will be suitable for your application or fit for any particular purpose, or will operate in" at 6254.01,-1368.94 h45
  text ".Layer_Name" at 502,-1396.77 h60
  text "ALTIUM DESIGNER VERSION:" at 12773.5,-1461.78 h45
  text "an implementation. TI and/or its licensors do not warrant that the design is production worthy. You should" at 6254.01,-1481.61 h45
  text "completely validate and test your design implementation to confirm the system functionality for your application." at 6299,-1594.28 h45
  text ".print_Scale" at 11318.5,-1595.1 h70
  text ".Application_BuildNumber" at 12824,-1595.1 h70
  text "2" at 3160.5,-1801.78 h70
  text "3" at 5649.84,-1801.78 h70
  text "4" at 8156.51,-1801.78 h70
  text "5" at 10655.5,-1801.78 h70
  text "6" at 13160.5,-1801.78 h70
M10 Fab Notes:
  drawing of 186 lines, arcs and shapes, not listed
  text "DESIGN INFORMATION" at 12306.02,5371.72 h60
  text "MIN. TRACK WIDTH:" at 11661.46,5191.72 h60
  text "6" at 12757.7,5191.73 h60
  text "MIL" at 12912.46,5191.72 h60
  text "MIN. CLEARANCE:" at 11661.46,5059.72 h60
  text "5.5" at 12697.7,5059.73 h60
  text "MIL" at 12912.46,5059.72 h60
  text "MIN. VIA PAD SIZE:" at 11661.46,4927.72 h60
  text "16" at 12727.71,4927.73 h60
  text "MIL" at 12912.46,4927.72 h60
  text "4 MIL" at 12356.46,4786.01 h60
  text "MINIMUM ANNULAR RING" at 11332.23,4781.73 h60
  text "PER" at 11532.23,4663.73 h60
  text "IPC-D-275 CLASS 2 LEVEL C" at 11752.23,4663.72 h60
  text "MIL, HOLES" at 13240.46,4551.44 h60
  text "+/-" at 12848,4550.73 h60
  text "+/-" at 13702,4550.73 h60
  text "REGISTRATION TOLERANCES:" at 11332.23,4545.72 h60
  text "METAL" at 12532,4545.72 h60
  text "MIL" at 14057.46,4545.72 h60
  text "MATERIAL:" at 11257.46,4336.27 h60
  text "FR-4 High Tg" at 12243.9,4195.93 h60
  text "FR-408" at 11678.46,4187.36 h60
  text "X" at 12090.46,4187.36 h60
  text "OTHER" at 13166.46,4187.36 h60
  text "62 MIL (1.6mm) +/-10%" at 11998.56,4024.65 h60
  text "47 MIL +/-10%" at 13580.56,4024.65 h60
  text "THICKNESS:" at 11332.23,4020.36 h60
  text "OTHER" at 13283.46,4020.36 h60
  text "X" at 13150.46,4016.36 h60
  text "TOLERANCE:" at 11332.23,3862.36 h60
  text "X" at 12171.53,3862.36 h60
  text "ANSI IPC-6012 TYPE 3 CLASS 2" at 12358.48,3862.36 h60
  text "OTHER +/-" at 12358.46,3706.36 h60
  text "BOW & TWIST:" at 11332.23,3549.36 h60
  text "X" at 12171.53,3549.36 h60
  text "ANSI IPC-6012 TYPE 3 CLASS 2" at 12358.48,3549.36 h60
  text "OTHER +/-" at 12358.46,3390.86 h60
  text "DRILLING:" at 11257.46,3252.36 h60
  text "REFERENCE:" at 11332.23,3135.36 h60
  text "X" at 11980.46,3135.36 h60
  text "AS SHOWN" at 12167.46,3135.36 h60
  text "X" at 12881.46,3135.36 h60
  text "NC_DRILL FILES" at 13018.46,3135.36 h60
  text "PTH MIN COPPER THICKNESS:" at 11332.23,2977.36 h60
  text "X" at 12674.46,2977.36 h60
  text "1MIL" at 12819.46,2977.36 h60
  text "OTHER" at 13316.46,2977.36 h60
  text "BOARD FINISH:" at 11257.46,2818.36 h60
  text "SILKSCREEN:" at 11412.68,2700.36 h60
  text "X" at 12361.46,2700.36 h60
  text "TOP" at 12487.46,2700.36 h60
  text "X" at 12871.46,2700.36 h60
  text "BOTTOM" at 12998.46,2700.36 h60
  text "SILKSCREEN COLOR:" at 11412.68,2533.36 h60
  text "X" at 12360.42,2533.36 h60
  text "WHITE" at 12487.46,2533.36 h60
  text "OTHER" at 12998.46,2533.36 h60
  text "SOLDER RESIST COLOR:" at 11412.68,2363.36 h60
  text "X" at 11980.42,2204.17 h60
  text "GREEN" at 12107.46,2204.17 h60
  text "BLUE" at 12698.46,2204.17 h60
  text "OTHER" at 13236.46,2204.17 h60
  text "IMMERSION GOLD (ENIG)" at 12318.46,2015.65 h60
  text "ENEPIG" at 13656,2012.36 h60
  text "SURFACE FINISH:" at 11257.46,2011.36 h60
  text "X" at 12131.51,2011.36 h60
  text "Please fill all 8 mil vias and plate & polish flat." at 100,1914 h72.83
  text "1" at 0,1911.72 h72.83
  text "IMM. TIN/SILVER OR EQUIV" at 11587,1854.36 h60
  text "OTHER" at 13018.46,1854.36 h60
  text "X" at 12134,1683 h60
  text "ARRAY/PANEL:" at 11257.46,1675.36 h60
  text "CUT AND TRIM PER MECH LAYER 1" at 12318.46,1671.08 h60
  text "N.C. ROUTE" at 12318.46,1519.36 h60
  text "V. SCORE" at 13184.46,1519.36 h60
  text "CERTIFICATION:" at 11257.46,1382.36 h60
  text "MATERIALS AND WORKMANSHIP FOR ALL PCBS" at 11982.46,1382.36 h60
  text "TO MEET OR EXCEED THE REQUIREMENTS OF:" at 11982.46,1284.36 h60
  text "X" at 11608.96,1147.86 h60
  text "ANSI IPC-A-600F CLASS ->" at 11747.96,1147.86 h60
  text "X" at 13387.02,1147.86 h60
  text "2" at 13505.96,1147.86 h60
  text "1" at 13190.96,1146.36 h60
  text "3" at 13859.96,1146.36 h60
  text "X" at 11611.02,988.36 h60
  text "UL 94V-0" at 11747.96,988.36 h60
  text "X" at 12423.02,988.36 h60
  text "RoHS" at 12559.96,988.36 h60
  text "OTHER" at 13204.36,988.36 h60
  text "PER ORDER" at 13601.42,988.36 h60
  text "ADDITIONAL REQUIREMENTS:" at 11257.46,847.36 h60
  text "MICROSECTION:" at 11332.23,732.36 h60
  text "YES" at 12237.96,732.36 h60
  text "REQUIRED" at 13099.46,576.22 h60
  text "BARE BOARD ELEC. TEST:" at 11332.23,573.36 h60
  text "NONE" at 12637.96,573.36 h60
  text "X" at 12972.46,573.36 h60
  text "PER ORDER" at 13691.46,573.36 h60
  text "MANUFACTURER'S UL:" at 11332.23,416.36 h60
  text "RAIL" at 12497.96,412.08 h60
  text "METAL" at 12989.77,412.08 h60
  text "X" at 13365,411.72 h60
  text "SILK" at 13501.46,412.08 h60
  text ".Layer_Name" at 502,-1396.77 h60
M11 Gerber Information:
  lines w10: -367,-1468.44 6233,-1468.44 ; -367,-1265.11 6235,-1265.11 ; -367,-1061.78 -367,-1671.78 3638,-1671.78 6235,-1671.78 6235,-1061.78 -366.5,-1061.78 -366.5,-1671.78 ; 2098,-1671.78 2098,-1061.78 ; 3365,-1265.11 3365,-1061.78 ; 4205,-1265.11 4205,-1061.78 ; 4224.5,2663.5 5800,2663.5 ; 4827,-1678.28 4827,-1475.44
  text "PLOT NAME =" at 4287.5,2732.66 h60
  text "BOARD #:" at 2173,-1193.94 h60
  text ".PRJ_Number" at 2718.5,-1193.94 h60
  text "REV:" at 3563,-1193.94 h60
  text ".PCB_Rev" at 3854.5,-1193.94 h60
  text "SVN REV:" at 4401,-1193.94 h60
  text ".VersionControl_RevNumber" at 4907,-1193.94 h60
  text ".plot_File_Name" at 502,-1602.61 h60
  text "GENERATED    :" at 2175,-1602.61 h60
  text ".Print_Date" at 3044.5,-1602.61 h60
  text ".Print_Time" at 3773.5,-1602.61 h60
  text "TEXAS INSTRUMENTS" at 5038,-1602.61 h60
M12 Stackup:
  drawing of 295 lines, arcs and shapes, not listed
  text "Layer" at 9542.84,7134.22 h60
  text "Name" at 9952.76,7134.22 h60
  text "Material" at 10882.5,7134.22 h60
  text "Thickness" at 11742.27,7134.22 h60
  text "Constant" at 12392.1,7134.22 h60
  text "Board Layer Stack" at 12961.96,7134.22 h60
  text "1" at 9542.84,7014.22 h60
  text "Top Overlay" at 9952.76,7014.22 h60
  text "2" at 9542.84,6894.22 h60
  text "Top Solder" at 9952.76,6894.22 h60
  text "Solder Resist" at 10882.5,6894.22 h60
  text "0.40mil" at 11742.27,6894.22 h60
  text "3.5" at 12392.1,6894.22 h60
  text "3" at 9542.84,6774.22 h60
  text "Top Layer" at 9952.76,6774.22 h60
  text "Copper" at 10882.5,6774.22 h60
  text "2.80mil" at 11742.27,6774.22 h60
  text "4" at 9542.84,6654.22 h60
  text "Dielectric1" at 9952.76,6654.22 h60
  text "FR-4 High Tg" at 10882.5,6654.22 h60
  text "4.60mil" at 11742.27,6654.22 h60
  text "4.8" at 12392.1,6654.22 h60
  text "5" at 9542.84,6534.22 h60
  text "MidLayer1" at 9952.76,6534.22 h60
  text "Copper" at 10882.5,6534.22 h60
  text "2.80mil" at 11742.27,6534.22 h60
  text "6" at 9542.84,6414.22 h60
  text "Dielectric2" at 9952.76,6414.22 h60
  text "FR-4 High Tg" at 10882.5,6414.22 h60
  text "25.80mil" at 11742.27,6414.22 h60
  text "4.8" at 12392.1,6414.22 h60
  text "7" at 9542.84,6294.22 h60
  text "MidLayer2" at 9952.76,6294.22 h60
  text "Copper" at 10882.5,6294.22 h60
  text "2.80mil" at 11742.27,6294.22 h60
  text "8" at 9542.84,6174.22 h60
  text "Dielectric3" at 9952.76,6174.22 h60
  text "FR-4 High Tg" at 10882.5,6174.22 h60
  text "4.60mil" at 11742.27,6174.22 h60
  text "4.8" at 12392.1,6174.22 h60
  text "9" at 9542.84,6054.22 h60
  text "Bottom Layer" at 9952.76,6054.22 h60
  text "Copper" at 10882.5,6054.22 h60
  text "2.80mil" at 11742.27,6054.22 h60
  text "10" at 9542.84,5934.22 h60
  text "Bottom Solder" at 9952.76,5934.22 h60
  text "Solder Resist" at 10882.5,5934.22 h60
  text "0.40mil" at 11742.27,5934.22 h60
  text "3.5" at 12392.1,5934.22 h60
  text "11" at 9542.84,5814.22 h60
  text "Bottom Overlay" at 9952.76,5814.22 h60
  text ".Layer_Name" at 5093,2938.51 h60
M13 Component Bodies Top:
  text ".Layer_Name" at 502,-1396.77 h60
M14 Component Bodies Bottom:
  text ".Layer_Name" at 502,-1396.77 h60
M15 Courtyards Top:
  text ".Layer_Name" at 502,-1396.77 h60
M16 Courtyards Bottom:
  text ".Layer_Name" at 502,-1396.77 h60
Drill Drawing:
  circle w10: c3769.72,1155.01 r27.63
  circle w10: c3769.72,906.37 r27.63
  circle w10: c3769.72,533.41 r27.63
  lines w10: 3742.09,146.63 3755.9,146.63 3769.72,132.82 3783.53,146.63 3797.34,146.63 3783.53,160.45 3797.34,174.26 3783.53,174.26 3769.72,188.07 3755.9,174.26 3742.09,174.26 3755.9,160.45 3742.09,146.63 ; 3742.09,257.14 3797.34,257.14 3797.34,312.39 3742.09,312.39 3742.09,257.14 ; 3742.09,381.46 3769.72,395.27 3797.34,381.46 3783.53,409.09 3797.34,436.71 3769.72,422.9 3742.09,436.71 3755.9,409.09 3742.09,381.46 ; 3742.09,657.73 3769.72,630.1 3797.34,657.73 3769.72,685.35 3742.09,657.73 ; 3742.09,809.67 3797.34,809.67 3769.72,754.42 3742.09,809.67 ; 3742.09,1003.06 3742.09,1016.87 3755.9,1030.69 3742.09,1044.5 3742.09,1058.31 3755.9,1058.31 3769.72,1044.5 3783.53,1058.31 3797.34,1058.31 3797.34,1044.5 3783.53,1030.69 3797.34,1016.87 3797.34,1003.06 3783.53,1003.06 3769.72,1016.87 3755.9,1003.06 3742.09,1003.06
  lines w12: 3692,95.52 6769.24,95.52 ; 3692,1214.4 6769.24,1214.4 ; 4029.86,-28.8 4029.86,1338.72 ; 4361.86,-28.8 4361.86,1338.72 ; 4998.43,-28.8 4998.43,1338.72 ; 5257.57,-28.8 5257.57,1338.72 ; 5632.72,-28.8 5632.72,1338.72 ; 6357.05,-28.8 6357.05,1338.72 ; 3692,-28.8 6769.24,-28.8 6769.24,1338.72 3692,1338.72 3692,-28.8
  text ".Layer_Name" at 5093,2938.51 h60
  text "Symbol" at 3766.59,1251.7 h72
  text "Quantity" at 4067.16,1251.7 h72
  text "Finished Hole Size" at 4399.16,1251.7 h72
  text "Plated" at 5035.72,1251.7 h72
  text "Hole Type" at 5294.86,1251.7 h72
  text "Drill Layer Pair" at 5670.02,1251.7 h72
  text "Tolerance" at 6394.35,1251.7 h72
  text "828" at 4067.16,1127.38 h60
  text "8.00mil (0.203mm)" at 4399.16,1127.38 h60
  text "PTH" at 5035.72,1127.38 h60
  text "Round" at 5294.86,1127.38 h60
  text "Top Layer - Bottom Layer" at 5670.02,1127.38 h60
  text "7" at 4067.16,1003.06 h60
  text "10.00mil (0.254mm)" at 4399.16,1003.06 h60
  text "PTH" at 5035.72,1003.06 h60
  text "Round" at 5294.86,1003.06 h60
  text "Top Layer - Bottom Layer" at 5670.02,1003.06 h60
  text "6" at 4067.16,878.74 h60
  text "12.00mil (0.305mm)" at 4399.16,878.74 h60
  text "PTH" at 5035.72,878.74 h60
  text "Round" at 5294.86,878.74 h60
  text "Top Layer - Bottom Layer" at 5670.02,878.74 h60
  text "17" at 4067.16,754.42 h60
  text "16.00mil (0.406mm)" at 4399.16,754.42 h60
  text "PTH" at 5035.72,754.42 h60
  text "Round" at 5294.86,754.42 h60
  text "Top Layer - Bottom Layer" at 5670.02,754.42 h60
  text "1" at 4067.16,630.1 h60
  text "20.00mil (0.508mm)" at 4399.16,630.1 h60
  text "PTH" at 5035.72,630.1 h60
  text "Round" at 5294.86,630.1 h60
  text "Top Layer - Bottom Layer" at 5670.02,630.1 h60
  text "4" at 4067.16,505.78 h60
  text "37.99mil (0.965mm)" at 4399.16,505.78 h60
  text "PTH" at 5035.72,505.78 h60
  text "Round" at 5294.86,505.78 h60
  text "Top Layer - Bottom Layer" at 5670.02,505.78 h60
  text "12" at 4067.16,381.46 h60
  text "40.00mil (1.016mm)" at 4399.16,381.46 h60
  text "PTH" at 5035.72,381.46 h60
  text "Round" at 5294.86,381.46 h60
  text "Top Layer - Bottom Layer" at 5670.02,381.46 h60
  text "1" at 4067.16,257.14 h60
  text "125.00mil (3.175mm)" at 4399.16,257.14 h60
  text "PTH" at 5035.72,257.14 h60
  text "Round" at 5294.86,257.14 h60
  text "Top Layer - Bottom Layer" at 5670.02,257.14 h60
  text "3" at 4067.16,132.82 h60
  text "125.00mil (3.175mm)" at 4399.16,132.82 h60
  text "PTH" at 5035.72,132.82 h60
  text "Round" at 5294.86,132.82 h60
  text "Top Layer - Bottom Layer" at 5670.02,132.82 h60
  text "879 Total" at 4067.16,8.5 h60

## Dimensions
0,1535.46 to 0,0 on M2 Board Dimensions
-75,-948.78 to 925,-948.78 on M2 Board Dimensions
0,0 to 3001,0 on M2 Board Dimensions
